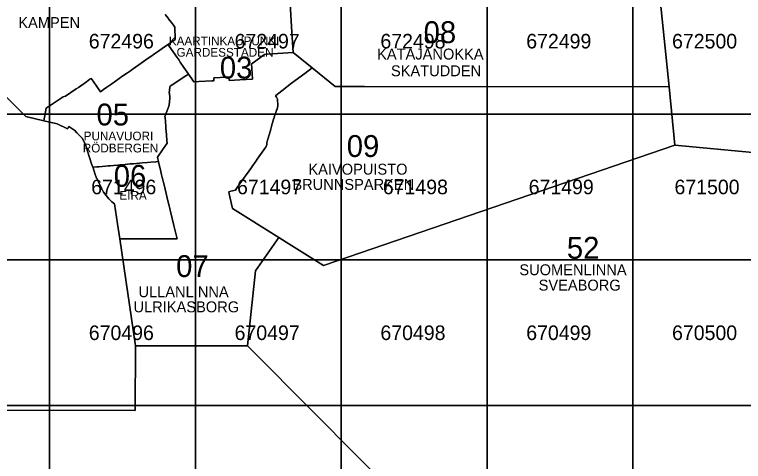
# Model space of a CAD drawing. Extents: x 25485000 to 25520000, y 6656775 to 6690000.
# Drawn here: x 25495760 to 25500758, y 6669617 to 6672682 of the extents above; entities that cross this region are included whole.
import ezdxf

# ---------------------------------------------------------------- set-up
doc = ezdxf.new("R2010")
doc.units = 0
doc.layers.add('Level 63', color=7, linetype='Continuous')

msp = doc.modelspace()

# ---------------------------------------------------------------- linework, layer by layer
at = {"layer": 'Level 63'}
for points in [[(25501011.9, 6673933.9), (25500113.5, 6673489.1), (25500143, 6673204.4), (25500174.3, 6672902.5), (25500179.5, 6672852.5), (25500248.5, 6672186.1), (25500288.5, 6671786.1), (25501016.8, 6671717.1)], [(25496793.3, 6672684), (25496806.3, 6672666.5), (25496822.8, 6672644.4), (25496834.8, 6672628.2), (25496848.7, 6672609.4), (25496857.8, 6672596.9), (25496859.2, 6672561.1), (25496859.7, 6672547.4), (25496861.1, 6672511.7), (25496824.1, 6672485.9), (25496812.1, 6672477.6), (25496820.4, 6672465.8), (25496847.6, 6672426.6), (25496874.3, 6672388.1), (25496887.6, 6672368.8), (25496895.9, 6672356.8), (25496921.2, 6672319.8), (25496943.7, 6672286.7), (25496952.2, 6672274.4), (25496975, 6672241), (25496981.8, 6672231.1), (25496989.2, 6672220.2), (25497022.9, 6672222.2), (25497112.3, 6672227.7), (25497127.1, 6672228.6), (25497126.5, 6672238.1), (25497124.9, 6672249.4), (25497214.3, 6672252.2), (25497229.1, 6672252.7), (25497230.2, 6672230.4), (25497304.9, 6672234.2), (25497391.1, 6672238.5), (25497386.6, 6672311.6), (25497384.7, 6672343.6), (25497388.3, 6672346.2), (25497404.1, 6672357.8), (25497457.3, 6672396.8), (25497473.3, 6672408.5), (25497491.9, 6672409.7), (25497670.7, 6672421.2), (25497661.7, 6672561.7), (25497646.7, 6672796.4)], [(25495679.4, 6672140.7), (25495836.2, 6671983.1), (25495960.7, 6671953.8), (25495976.9, 6672039.3), (25496052.1, 6672091.8), (25496093.8, 6672117.9), (25496109.2, 6672122.3), (25496182.1, 6672172.1), (25496197.7, 6672183), (25496251.8, 6672220.9), (25496276.5, 6672238.2), (25496285.3, 6672244.4), (25496298.9, 6672224.9), (25496348.4, 6672153.5), (25496368.7, 6672167.6), (25496392.3, 6672183.9), (25496413.9, 6672198.9), (25496426.1, 6672207.2), (25496452.1, 6672225.6), (25496477.5, 6672243.4), (25496502.7, 6672261.2), (25496528, 6672279), (25496553.4, 6672296.9), (25496565.4, 6672305.2), (25496588.9, 6672321.6), (25496612.3, 6672338), (25496659.2, 6672370.9), (25496682.8, 6672387.4), (25496694.5, 6672395.7), (25496718.2, 6672412.2), (25496738.7, 6672426.5), (25496787.6, 6672460.6), (25496812.1, 6672477.6), (25496824.1, 6672485.9), (25496861.1, 6672511.7), (25496859.7, 6672547.4), (25496859.2, 6672561.1), (25496857.8, 6672596.9), (25496848.7, 6672609.4), (25496834.8, 6672628.2), (25496822.8, 6672644.4), (25496806.3, 6672666.5), (25496793.3, 6672684)], [(25495369, 6669969), (25496587.4, 6669967.5), (25496587.9, 6670410.5), (25496480.6, 6671144.7), (25496465.7, 6671247), (25496445.6, 6671384.7), (25496427.5, 6671398.8), (25496406.1, 6671418.8), (25496387, 6671441), (25496370.3, 6671465.1), (25496356.2, 6671490.8), (25496329.1, 6671549.6), (25496324, 6671560.5), (25496320.7, 6671559.4), (25496310, 6671592.8), (25496298.1, 6671630.1), (25496296.4, 6671635), (25496287.7, 6671659.5), (25496260.3, 6671745.2), (25496245.8, 6671790.5), (25496222, 6671834.9), (25496187.2, 6671871.6), (25496173, 6671886.7), (25496131.4, 6671915.2), (25496122.8, 6671898.2), (25496052.7, 6671932.2), (25495960.7, 6671953.8), (25495836.2, 6671983.1), (25495679.4, 6672140.7)], [(25506579.5, 6668434.3), (25501637.6, 6667310.5), (25500575.9, 6667170.8), (25499970.4, 6667780), (25497406.6, 6670359.6), (25497356.9, 6670409.6), (25496637.9, 6670410.5), (25496587.9, 6670410.5), (25496587.4, 6669967.5), (25495369, 6669969), (25494289.6, 6669969.4), (25494289.1, 6669645.1), (25492634.2, 6669822.8), (25491000.6, 6669998.2), (25490932.5, 6669294), (25490866.6, 6668614.1), (25487917.1, 6665229.6), (25489108.9, 6662564), (25491530.4, 6657152.9), (25491699.2, 6656775.5), (25493980.3, 6658047.6), (25507390.7, 6664195.2)]]:
    msp.add_lwpolyline(points, dxfattribs=at)
for points in [[(25497653, 6672807), (25497646.7, 6672796.4), (25497661.7, 6672561.7), (25497670.7, 6672421.2), (25497800.7, 6672316.1), (25497957.8, 6672188.9), (25498158.3, 6672188.6), (25500248.5, 6672186.1), (25500179.5, 6672852.5), (25498837.8, 6672854.1), (25498811.9, 6673003.3), (25498761.9, 6673013.3), (25498613.5, 6673043), (25498442.7, 6673077.2), (25498384.2, 6673077.3), (25498277.7, 6673077.4), (25498122.4, 6673077.6), (25497727.9, 6672932.2)], [(25495000, 6672000), (25496000, 6672000), (25496000, 6673000), (25495000, 6673000)], [(25496000, 6672000), (25497000, 6672000), (25497000, 6673000), (25496000, 6673000)], [(25497000, 6672000), (25498000, 6672000), (25498000, 6673000), (25497000, 6673000)], [(25498000, 6672000), (25499000, 6672000), (25499000, 6673000), (25498000, 6673000)], [(25499000, 6672000), (25500000, 6672000), (25500000, 6673000), (25499000, 6673000)], [(25500000, 6672000), (25501000, 6672000), (25501000, 6673000), (25500000, 6673000)], [(25495960.7, 6671953.8), (25496052.7, 6671932.2), (25496122.8, 6671898.2), (25496131.4, 6671915.2), (25496173, 6671886.7), (25496187.2, 6671871.6), (25496222, 6671834.9), (25496245.8, 6671790.5), (25496260.3, 6671745.2), (25496287.7, 6671659.5), (25496296.4, 6671635), (25496324.7, 6671637.4), (25496337, 6671638.5), (25496360.2, 6671640.5), (25496382.5, 6671642.4), (25496400.3, 6671643.9), (25496415.8, 6671645.4), (25496438.2, 6671647.3), (25496467.9, 6671649.9), (25496481.2, 6671651.1), (25496499.1, 6671652.7), (25496517, 6671654.3), (25496534.9, 6671655.9), (25496552.9, 6671657.5), (25496575.5, 6671659.4), (25496615.4, 6671663), (25496636.3, 6671664.8), (25496671.8, 6671668), (25496693.8, 6671669.9), (25496727.7, 6671672.9), (25496746.3, 6671674.5), (25496742.1, 6671692), (25496739.3, 6671703.6), (25496773.9, 6671755), (25496805.1, 6671801.3), (25496803.9, 6671816.2), (25496800.5, 6671859.4), (25496797.2, 6671900.9), (25496796.1, 6671912.4), (25496793.4, 6671947.9), (25496791.2, 6671977.5), (25496790.8, 6671983), (25496796.8, 6671998.9), (25496812.8, 6672041.8), (25496815.9, 6672047.3), (25496818.9, 6672060.8), (25496823.5, 6672109.2), (25496823.9, 6672114.2), (25496820.9, 6672142.3), (25496819.7, 6672144.1), (25496824.3, 6672184.8), (25496822.7, 6672187.1), (25496827.2, 6672190.2), (25496834.3, 6672195), (25496934.9, 6672262.7), (25496952.2, 6672274.4), (25496943.7, 6672286.7), (25496921.2, 6672319.8), (25496895.9, 6672356.8), (25496887.6, 6672368.8), (25496874.3, 6672388.1), (25496847.6, 6672426.6), (25496820.4, 6672465.8), (25496812.1, 6672477.6), (25496787.6, 6672460.6), (25496738.7, 6672426.5), (25496718.2, 6672412.2), (25496694.5, 6672395.7), (25496682.8, 6672387.4), (25496659.2, 6672370.9), (25496612.3, 6672338), (25496588.9, 6672321.6), (25496565.4, 6672305.2), (25496553.4, 6672296.9), (25496528, 6672279), (25496502.7, 6672261.2), (25496477.5, 6672243.4), (25496452.1, 6672225.6), (25496426.1, 6672207.2), (25496413.9, 6672198.9), (25496392.3, 6672183.9), (25496368.7, 6672167.6), (25496348.4, 6672153.5), (25496298.9, 6672224.9), (25496285.3, 6672244.4), (25496276.5, 6672238.2), (25496251.8, 6672220.9), (25496197.7, 6672183), (25496182.1, 6672172.1), (25496109.2, 6672122.3), (25496093.8, 6672117.9), (25496052.1, 6672091.8), (25495976.9, 6672039.3)], [(25496480.6, 6671144.7), (25496587.9, 6670410.5), (25496637.9, 6670410.5), (25497356.9, 6670409.6), (25497411.6, 6670925.7), (25497571.8, 6671153.4), (25497255, 6671352.3), (25497248.2, 6671380.9), (25497231.3, 6671452.4), (25497227.9, 6671466.8), (25497242.5, 6671470.3), (25497274.4, 6671478), (25497282.3, 6671489.2), (25497302.7, 6671518.2), (25497332.1, 6671560.1), (25497347.5, 6671582.1), (25497363, 6671604.1), (25497383.3, 6671633.1), (25497393.7, 6671647.8), (25497415.3, 6671678.8), (25497423.5, 6671690.5), (25497445.6, 6671721.7), (25497479.6, 6671769.8), (25497481, 6671771.7), (25497482.1, 6671773.3), (25497483, 6671774.9), (25497483.8, 6671776.3), (25497484.6, 6671777.8), (25497485.3, 6671779.3), (25497485.7, 6671780.2), (25497486.1, 6671781.1), (25497487.1, 6671783.7), (25497487.5, 6671784.9), (25497487.8, 6671786.2), (25497488.4, 6671788.6), (25497488.7, 6671790), (25497489.1, 6671792.2), (25497489.4, 6671794.9), (25497489.5, 6671797.5), (25497489.5, 6671800), (25497489.3, 6671803.5), (25497494.5, 6671821.7), (25497507.1, 6671865.3), (25497515.9, 6671896.1), (25497521.4, 6671915.2), (25497524.7, 6671926.7), (25497530.7, 6671947.4), (25497536.3, 6671966.8), (25497536.9, 6671966.6), (25497540.4, 6671978.8), (25497553.8, 6672017.5), (25497556.8, 6672026.2), (25497559.6, 6672034.2), (25497565.7, 6672056.6), (25497561.9, 6672102.2), (25497555.8, 6672114.9), (25497549.4, 6672125.9), (25497562.8, 6672136.4), (25497601.2, 6672166.6), (25497614.8, 6672177.3), (25497658.5, 6672211.7), (25497750.6, 6672279.3), (25497800.7, 6672316.1), (25497670.7, 6672421.2), (25497491.9, 6672409.7), (25497473.3, 6672408.5), (25497457.3, 6672396.8), (25497404.1, 6672357.8), (25497388.3, 6672346.2), (25497384.7, 6672343.6), (25497386.6, 6672311.6), (25497391.1, 6672238.5), (25497304.9, 6672234.2), (25497230.2, 6672230.4), (25497229.1, 6672252.7), (25497214.3, 6672252.2), (25497124.9, 6672249.4), (25497126.5, 6672238.1), (25497127.1, 6672228.6), (25497112.3, 6672227.7), (25497022.9, 6672222.2), (25496989.2, 6672220.2), (25496981.8, 6672231.1), (25496975, 6672241), (25496952.2, 6672274.4), (25496934.9, 6672262.7), (25496834.3, 6672195), (25496827.2, 6672190.2), (25496822.7, 6672187.1), (25496824.3, 6672184.8), (25496819.7, 6672144.1), (25496820.9, 6672142.3), (25496823.9, 6672114.2), (25496823.5, 6672109.2), (25496818.9, 6672060.8), (25496815.9, 6672047.3), (25496812.8, 6672041.8), (25496796.8, 6671998.9), (25496790.8, 6671983), (25496791.2, 6671977.5), (25496793.4, 6671947.9), (25496796.1, 6671912.4), (25496797.2, 6671900.9), (25496800.5, 6671859.4), (25496803.9, 6671816.2), (25496805.1, 6671801.3), (25496773.9, 6671755), (25496739.3, 6671703.6), (25496742.1, 6671692), (25496746.3, 6671674.5), (25496747.2, 6671670.6), (25496759.9, 6671617.8), (25496768.2, 6671583.2), (25496772.4, 6671565.8), (25496776.5, 6671548.5), (25496780.7, 6671531.1), (25496784.9, 6671513.5), (25496813, 6671396.3), (25496819.3, 6671370.1), (25496823.8, 6671351.4), (25496824.4, 6671349), (25496828.5, 6671331.5), (25496851.5, 6671235.8), (25496873.4, 6671144.2), (25496530.6, 6671144.6)], [(25497479.6, 6671769.8), (25497445.6, 6671721.7), (25497423.5, 6671690.5), (25497415.3, 6671678.8), (25497393.7, 6671647.8), (25497383.3, 6671633.1), (25497363, 6671604.1), (25497347.5, 6671582.1), (25497332.1, 6671560.1), (25497302.7, 6671518.2), (25497282.3, 6671489.2), (25497274.4, 6671478), (25497242.5, 6671470.3), (25497227.9, 6671466.8), (25497231.3, 6671452.4), (25497248.2, 6671380.9), (25497255, 6671352.3), (25497571.8, 6671153.4), (25497621.7, 6671122), (25497878.5, 6670960.8), (25500288.5, 6671786.1), (25500248.5, 6672186.1), (25498158.3, 6672188.6), (25497957.8, 6672188.9), (25497800.7, 6672316.1), (25497750.6, 6672279.3), (25497658.5, 6672211.7), (25497614.8, 6672177.3), (25497601.2, 6672166.6), (25497562.8, 6672136.4), (25497549.4, 6672125.9), (25497555.8, 6672114.9), (25497561.9, 6672102.2), (25497565.7, 6672056.6), (25497559.6, 6672034.2), (25497556.8, 6672026.2), (25497553.8, 6672017.5), (25497540.4, 6671978.8), (25497536.9, 6671966.6), (25497536.3, 6671966.8), (25497530.7, 6671947.4), (25497524.7, 6671926.7), (25497521.4, 6671915.2), (25497515.9, 6671896.1), (25497507.1, 6671865.3), (25497494.5, 6671821.7), (25497489.3, 6671803.5), (25497489.5, 6671800), (25497489.5, 6671797.5), (25497489.4, 6671794.9), (25497489.1, 6671792.2), (25497488.7, 6671790), (25497488.4, 6671788.6), (25497487.8, 6671786.2), (25497487.5, 6671784.9), (25497487.1, 6671783.7), (25497486.1, 6671781.1), (25497485.7, 6671780.2), (25497485.3, 6671779.3), (25497484.6, 6671777.8), (25497483.8, 6671776.3), (25497483, 6671774.9), (25497482.1, 6671773.3), (25497481, 6671771.7)], [(25495000, 6671000), (25496000, 6671000), (25496000, 6672000), (25495000, 6672000)], [(25496000, 6671000), (25497000, 6671000), (25497000, 6672000), (25496000, 6672000)], [(25497000, 6671000), (25498000, 6671000), (25498000, 6672000), (25497000, 6672000)], [(25498000, 6671000), (25499000, 6671000), (25499000, 6672000), (25498000, 6672000)], [(25499000, 6671000), (25500000, 6671000), (25500000, 6672000), (25499000, 6672000)], [(25500000, 6671000), (25501000, 6671000), (25501000, 6672000), (25500000, 6672000)], [(25497356.9, 6670409.6), (25497406.6, 6670359.6), (25499970.4, 6667780), (25500575.9, 6667170.8), (25501637.6, 6667310.5), (25501556.1, 6669404.6), (25501232, 6669785), (25501232.7, 6670417.8), (25501234.3, 6671696.4), (25501016.8, 6671717.1), (25500288.5, 6671786.1), (25497878.5, 6670960.8), (25497621.7, 6671122), (25497571.8, 6671153.4), (25497411.6, 6670925.7)], [(25496296.4, 6671635), (25496298.1, 6671630.1), (25496310, 6671592.8), (25496320.7, 6671559.4), (25496324, 6671560.5), (25496329.1, 6671549.6), (25496356.2, 6671490.8), (25496370.3, 6671465.1), (25496387, 6671441), (25496406.1, 6671418.8), (25496427.5, 6671398.8), (25496445.6, 6671384.7), (25496465.7, 6671247), (25496480.6, 6671144.7), (25496530.6, 6671144.6), (25496873.4, 6671144.2), (25496851.5, 6671235.8), (25496828.5, 6671331.5), (25496824.4, 6671349), (25496823.8, 6671351.4), (25496819.3, 6671370.1), (25496813, 6671396.3), (25496784.9, 6671513.5), (25496780.7, 6671531.1), (25496776.5, 6671548.5), (25496772.4, 6671565.8), (25496768.2, 6671583.2), (25496759.9, 6671617.8), (25496747.2, 6671670.6), (25496746.3, 6671674.5), (25496727.7, 6671672.9), (25496693.8, 6671669.9), (25496671.8, 6671668), (25496636.3, 6671664.8), (25496615.4, 6671663), (25496575.5, 6671659.4), (25496552.9, 6671657.5), (25496534.9, 6671655.9), (25496517, 6671654.3), (25496499.1, 6671652.7), (25496481.2, 6671651.1), (25496467.9, 6671649.9), (25496438.2, 6671647.3), (25496415.8, 6671645.4), (25496400.3, 6671643.9), (25496382.5, 6671642.4), (25496360.2, 6671640.5), (25496337, 6671638.5), (25496324.7, 6671637.4)], [(25495000, 6670000), (25496000, 6670000), (25496000, 6671000), (25495000, 6671000)], [(25496000, 6670000), (25497000, 6670000), (25497000, 6671000), (25496000, 6671000)], [(25497000, 6670000), (25498000, 6670000), (25498000, 6671000), (25497000, 6671000)], [(25498000, 6670000), (25499000, 6670000), (25499000, 6671000), (25498000, 6671000)], [(25499000, 6670000), (25500000, 6670000), (25500000, 6671000), (25499000, 6671000)], [(25500000, 6670000), (25501000, 6670000), (25501000, 6671000), (25500000, 6671000)], [(25495000, 6669000), (25496000, 6669000), (25496000, 6670000), (25495000, 6670000)], [(25496000, 6669000), (25497000, 6669000), (25497000, 6670000), (25496000, 6670000)], [(25497000, 6669000), (25498000, 6669000), (25498000, 6670000), (25497000, 6670000)], [(25498000, 6669000), (25499000, 6669000), (25499000, 6670000), (25498000, 6670000)], [(25499000, 6669000), (25500000, 6669000), (25500000, 6670000), (25499000, 6670000)], [(25500000, 6669000), (25501000, 6669000), (25501000, 6670000), (25500000, 6670000)]]:
    msp.add_lwpolyline(points, close=True, dxfattribs=at)

# ---------------------------------------------------------------- texts
for s, height, p in [('KAMPEN', 75, (25495785.1, 6672590.1)), ('08', 150, (25498564.9, 6672486.5)), ('672496', 100, (25496268.5, 6672450)), ('KAARTINKAUPUNKI', 60, (25496817.3, 6672471.7)), ('672497', 100, (25497268.5, 6672450)), ('672498', 100, (25498268.5, 6672450)), ('672499', 100, (25499268.5, 6672450)), ('672500', 100, (25500268.5, 6672450)), ('GARDESSTADEN', 60, (25496870.6, 6672393.5)), ('KATAJANOKKA', 75, (25498245.8, 6672374)), ('03', 150, (25497167.3, 6672243.4)), ('SKATUDDEN', 75, (25498340.6, 6672259.3)), ('05', 150, (25496321.3, 6671921.8)), ('PUNAVUORI', 60, (25496233.6, 6671819.6)), ('09', 150, (25498037.6, 6671705.6)), ('RÖDBERGEN', 60, (25496227.3, 6671736.8)), ('06', 150, (25496439.7, 6671501.1)), ('KAIVOPUISTO', 75, (25497774.3, 6671584.4)), ('671496', 100, (25496285.1, 6671450)), ('671497', 100, (25497285.1, 6671450)), ('BRUNNSPARKEN', 75, (25497664.4, 6671479.9)), ('671498', 100, (25498285.1, 6671450)), ('671499', 100, (25499285.1, 6671450)), ('671500', 100, (25500285.1, 6671450)), ('EIRA', 60, (25496478.6, 6671412.1)), ('52', 150, (25499547, 6671007.7)), ('07', 150, (25496867.4, 6670882)), ('SUOMENLINNA', 75, (25499221.3, 6670894.6)), ('SVEABORG', 75, (25499353.4, 6670789.1)), ('ULLANLINNA', 75, (25496609.1, 6670743.6)), ('ULRIKASBORG', 75, (25496574.9, 6670640.1)), ('670496', 100, (25496268.5, 6670450)), ('670497', 100, (25497268.5, 6670450)), ('670498', 100, (25498268.5, 6670450)), ('670499', 100, (25499268.5, 6670450)), ('670500', 100, (25500268.5, 6670450))]:
    msp.add_text(s, height=height, dxfattribs=at).set_placement(p)

doc.saveas('drawing.dxf')
